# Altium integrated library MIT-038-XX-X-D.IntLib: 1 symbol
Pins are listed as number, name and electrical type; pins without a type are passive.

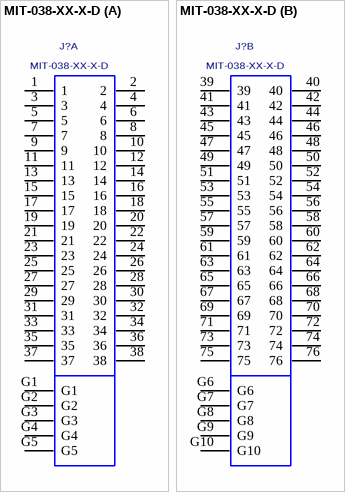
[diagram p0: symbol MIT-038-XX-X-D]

## MIT-038-XX-X-D
designator J?
.635mm DOUBLE ROW HS TERMINAL ASSEMBLY.; MANUFACTURER: SAMTEC
footprint MIT-038-XX-X-D
part A pins: 1, 2, 3, 4, 5, 6, 7, 8, 9, 10, 11, 12, 13, 14, 15, 16, 17, 18, 19, 20, 21, 22, 23, 24, 25, 26, 27, 28, 29, 30, 31, 32, 33, 34, 35, 36, 37, 38, G1, G2, G3, G4, G5
part B pins: 39, 40, 41, 42, 43, 44, 45, 46, 47, 48, 49, 50, 51, 52, 53, 54, 55, 56, 57, 58, 59, 60, 61, 62, 63, 64, 65, 66, 67, 68, 69, 70, 71, 72, 73, 74, 75, 76, G6, G7, G8, G9, G10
